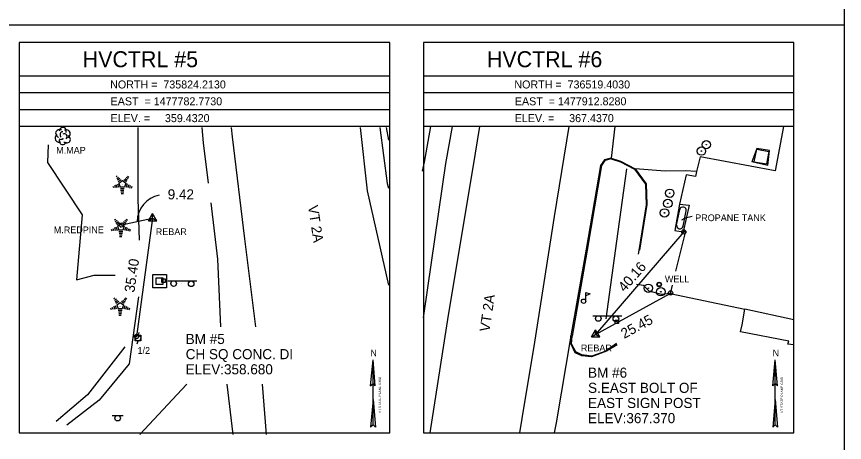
# Model space of a CAD drawing. Extents: x 1478584 to 1479224, y 735365 to 735785.
# Drawn here: x 1478978.7 to 1479224.5, y 735534.2 to 735660.7 of the extents above; entities that cross this region are included whole.
import ezdxf

# ---------------------------------------------------------------- set-up
doc = ezdxf.new("R2010")
doc.units = 0
for name, color, linetype in [('C_A', 7, 'Continuous'), ('CBP', 7, 'Continuous'), ('CPBM', 7, 'Continuous'), ('CPSM', 7, 'Continuous'), ('Default', 7, 'Continuous'), ('DS', 7, 'Continuous'), ('L_C', 7, 'Continuous'), ('LAHR', 7, 'Continuous'), ('LAPB', 7, 'Continuous'), ('LBC', 7, 'Continuous'), ('LBF', 7, 'Continuous'), ('LELB', 7, 'Continuous'), ('LFNC', 7, 'Continuous'), ('LMB', 7, 'Continuous'), ('LS', 7, 'Continuous'), ('LTC', 7, 'Continuous'), ('LTD', 7, 'Continuous'), ('NBL1', 7, 'Continuous'), ('NBL2', 7, 'Continuous'), ('NNA_P', 7, 'Continuous'), ('PET', 7, 'Continuous'), ('PSP', 7, 'Continuous'), ('PSU', 7, 'Continuous'), ('RC', 7, 'Continuous'), ('RDP', 7, 'Continuous'), ('RGP', 7, 'Continuous'), ('SSGN', 7, 'Continuous'), ('U_A', 7, 'Continuous'), ('U_C', 7, 'Continuous'), ('UP', 7, 'Continuous'), ('UWW', 7, 'Continuous')]:
    doc.layers.add(name, color=color, linetype=linetype)

msp = doc.modelspace()

# ---------------------------------------------------------------- linework, layer by layer
at = {"layer": 'CBP'}
for centre, radius in [((1479009.88, 735598.79), 0.625), ((1479009.88, 735598.79), 0.0833), ((1479176.77, 735596.72), 0.625), ((1479176.77, 735596.72), 0.0833), ((1479172.85, 735578.61), 0.625), ((1479172.85, 735578.61), 0.0833), ((1479014.32, 735565.69), 0.625), ((1479014.32, 735565.69), 0.0833)]:
    msp.add_circle(centre, radius, dxfattribs=at)
at = {"layer": 'CPBM'}
for p, q in [((1479021.79, 735581.74), (1479021.79, 735582.74)), ((1479021.79, 735582.74), (1479022.79, 735582.74)), ((1479022.79, 735581.74), (1479021.79, 735581.74)), ((1479022.3, 735582.24), (1479022.3, 735582.24)), ((1479022.3, 735582.24), (1479022.3, 735582.24)), ((1479022.79, 735582.74), (1479022.79, 735581.74)), ((1479156.4, 735569.53), (1479156.4, 735570.53)), ((1479156.4, 735570.53), (1479157.4, 735570.53)), ((1479157.4, 735569.53), (1479156.4, 735569.53)), ((1479156.9, 735570.03), (1479156.9, 735570.03)), ((1479156.9, 735570.03), (1479156.9, 735570.03)), ((1479157.4, 735570.53), (1479157.4, 735569.53))]:
    msp.add_line(p, q, dxfattribs=at)
at = {"layer": 'CPSM'}
for p, q in [((1479017.84, 735600.05), (1479019.09, 735602.21)), ((1479017.84, 735600.05), (1479019.09, 735600.77)), ((1479017.85, 735600.05), (1479019.1, 735602.22)), ((1479017.85, 735600.05), (1479019.1, 735600.77)), ((1479020.34, 735600.05), (1479019.09, 735602.21)), ((1479019.09, 735600.77), (1479019.09, 735602.21)), ((1479019.09, 735600.77), (1479019.09, 735600.77)), ((1479019.09, 735600.77), (1479020.34, 735600.05)), ((1479020.35, 735600.05), (1479019.1, 735602.22)), ((1479019.1, 735600.77), (1479019.1, 735602.22)), ((1479019.1, 735600.77), (1479019.1, 735600.77)), ((1479019.1, 735600.77), (1479020.35, 735600.05)), ((1479017.84, 735600.05), (1479020.34, 735600.05)), ((1479017.85, 735600.05), (1479020.35, 735600.05)), ((1479149.35, 735565.53), (1479150.6, 735567.69)), ((1479149.35, 735565.53), (1479150.6, 735566.25)), ((1479151.85, 735565.53), (1479150.6, 735567.69)), ((1479150.6, 735566.25), (1479150.6, 735567.69)), ((1479150.6, 735566.25), (1479150.6, 735566.25)), ((1479150.6, 735566.25), (1479151.85, 735565.53)), ((1479149.35, 735565.53), (1479151.85, 735565.53))]:
    msp.add_line(p, q, dxfattribs=at)
at = {"layer": 'Default'}
for p, q in [((1479174.63, 735598.77), (1479175.56, 735603.4)), ((1479176.61, 735598.48), (1479177.52, 735603)), ((1479009.88, 735598.79), (1479019.1, 735600.77)), ((1479019.1, 735600.77), (1479014.32, 735565.69)), ((1479176.59, 735598.38), (1479176.61, 735598.48)), ((1479176.77, 735596.72), (1479150.6, 735566.25)), ((1479150.6, 735566.25), (1479172.71, 735578.42))]:
    msp.add_line(p, q, dxfattribs=at)
for centre, radius, start, end in [((1479022.57, 735599.71), 8.08, 100.8349, 179.5195), ((1479176.53, 735603.12), 1, 353.0077, 164.0721), ((1479179.7, 735594.51), 6.76, 93.3569, 122.6023), ((1479175.63, 735598.67), 1.01, 174.3588, 342.721)]:
    msp.add_arc(centre, radius, start, end, dxfattribs=at)
at = {"layer": 'DS'}
for p, q in [((1479019.16, 735584.12), (1479023.16, 735584.12)), ((1479019.16, 735580.12), (1479019.16, 735584.12)), ((1479020.16, 735581.12), (1479020.16, 735583.12)), ((1479020.16, 735583.12), (1479022.16, 735583.12)), ((1479022.16, 735583.12), (1479022.16, 735581.12)), ((1479023.16, 735584.12), (1479023.16, 735580.12)), ((1479022.16, 735581.12), (1479020.16, 735581.12)), ((1479021.17, 735582.12), (1479021.17, 735582.12)), ((1479021.17, 735582.12), (1479021.17, 735582.12)), ((1479023.16, 735580.12), (1479019.16, 735580.12))]:
    msp.add_line(p, q, dxfattribs=at)
at = {"layer": 'LAHR'}
for points in [[(1479153.75, 735570.91), (1479156.85, 735593.93), (1479159.91, 735615.44)], [(1479010.88, 735562.58), (1478999.76, 735548.34), (1478990.41, 735540.43)]]:
    msp.add_lwpolyline(points, dxfattribs=at)
at = {"layer": 'LAPB'}
msp.add_lwpolyline([(1478988.09, 735622.57), (1478987.9, 735617.37), (1478998.19, 735601.76), (1478996.45, 735582.53), (1479001.78, 735583.87), (1479008.01, 735583.9)], dxfattribs=at)
at = {"layer": 'LBC'}
for points in [[(1479206.37, 735627.99), (1479203.93, 735614.91), (1479181.67, 735619.06), (1479180.59, 735614.7), (1479180.23, 735613.14), (1479177.47, 735613.7), (1479175.46, 735604.94), (1479178.35, 735604.65), (1479176.62, 735596.73), (1479177.29, 735596.97), (1479174.35, 735585.07)], [(1479209.4, 735627.98), (1479209.36, 735627.99)], [(1479173.32, 735580.9), (1479172.71, 735578.42), (1479194.91, 735573.74)], [(1479209.4, 735570.65), (1479194.91, 735573.74)]]:
    msp.add_lwpolyline(points, dxfattribs=at)
at = {"layer": 'LBF'}
msp.add_lwpolyline([(1479209.4, 735563.16), (1479207.65, 735563.4), (1479207.96, 735564.27), (1479193.59, 735567), (1479194.06, 735569.09), (1479194.91, 735573.74)], dxfattribs=at)
at = {"layer": 'LELB'}
for points in [[(1479088.43, 735627.72), (1479089.08, 735624.02)], [(1479201.76, 735616.43), (1479202.19, 735620.86), (1479198.44, 735621.54), (1479197.01, 735617.58)], [(1479201.76, 735616.43), (1479197.01, 735617.58)], [(1479162.35, 735615.46), (1479165.56, 735611.01), (1479165.84, 735604.85), (1479163.58, 735591.27)]]:
    msp.add_lwpolyline(points, dxfattribs=at)
at = {"layer": 'LFNC'}
for points in [[(1479015.22, 735594.29), (1479014.82, 735606.55), (1479014.8, 735627.72)], [(1479014.94, 735577.42), (1479012.14, 735557.51), (1479003.2, 735546.79), (1478993.66, 735539.34)]]:
    msp.add_lwpolyline(points, dxfattribs=at)
at = {"layer": 'LMB'}
for p, q in [((1479147.68, 735578.75), (1479148.98, 735578.36)), ((1479147.69, 735576.15), (1479147.69, 735578.75)), ((1479147.69, 735577.85), (1479148.97, 735578.35)), ((1479147.03, 735576.14), (1479147.03, 735576.14))]:
    msp.add_line(p, q, dxfattribs=at)
msp.add_circle((1479147.03, 735576.14), 0.656, dxfattribs=at)
at = {"layer": 'LS'}
for points in [[(1479197.71, 735617.55), (1479198.45, 735621.32), (1479201.97, 735620.63), (1479201.35, 735616.95)], [(1479197.71, 735617.55), (1479201.35, 735616.95)], [(1479175.46, 735604.94), (1479174.1, 735597.15), (1479176.62, 735596.73)]]:
    msp.add_lwpolyline(points, dxfattribs=at)
at = {"layer": 'LTC'}
for p, q in [((1479008.24, 735613.09), (1479008.6, 735613.34)), ((1479008.45, 735612.62), (1479008.98, 735613)), ((1479008.66, 735612.15), (1479009.36, 735612.67)), ((1479010.9, 735612.63), (1479011.58, 735612.14)), ((1479011.27, 735612.98), (1479011.82, 735612.58)), ((1479011.64, 735613.33), (1479012.06, 735613.02)), ((1479007.27, 735610.36), (1479007.43, 735609.9)), ((1479007.73, 735610.58), (1479007.94, 735609.93)), ((1479008.18, 735610.8), (1479008.46, 735609.96)), ((1479008.64, 735611.01), (1479008.97, 735609.99)), ((1479008.87, 735611.69), (1479009.75, 735612.33)), ((1479009.09, 735611.23), (1479010.11, 735611.97)), ((1479009.09, 735611.23), (1479009.48, 735610.04)), ((1479010.11, 735611.97), (1479011.1, 735611.24)), ((1479010.53, 735612.28), (1479011.34, 735611.69)), ((1479011.1, 735611.24), (1479010.71, 735610.04)), ((1479011.54, 735610.97), (1479011.2, 735609.93)), ((1479011.99, 735610.72), (1479011.7, 735609.84)), ((1479012.43, 735610.47), (1479012.19, 735609.74)), ((1479012.87, 735610.22), (1479012.69, 735609.65)), ((1479010.71, 735610.04), (1479009.48, 735610.04)), ((1479010.67, 735609.54), (1479009.53, 735609.54)), ((1479010.59, 735609.04), (1479009.6, 735609.04)), ((1479010.51, 735608.54), (1479009.67, 735608.54)), ((1479010.42, 735608.04), (1479009.75, 735608.04)), ((1479007.79, 735600.28), (1479008.15, 735600.53)), ((1479011.19, 735600.52), (1479011.61, 735600.21)), ((1479007.28, 735597.77), (1479007.49, 735597.12)), ((1479007.74, 735597.99), (1479008.01, 735597.15)), ((1479008, 735599.81), (1479008.53, 735600.2)), ((1479008.19, 735598.21), (1479008.52, 735597.19)), ((1479008.21, 735599.35), (1479008.92, 735599.86)), ((1479008.42, 735598.88), (1479009.3, 735599.52)), ((1479008.65, 735598.42), (1479009.66, 735599.16)), ((1479008.65, 735598.42), (1479009.03, 735597.23)), ((1479009.66, 735599.16), (1479010.66, 735598.43)), ((1479010.08, 735599.47), (1479010.89, 735598.88)), ((1479010.66, 735598.43), (1479010.26, 735597.23)), ((1479010.45, 735599.82), (1479011.13, 735599.33)), ((1479011.09, 735598.16), (1479010.76, 735597.12)), ((1479010.82, 735600.17), (1479011.37, 735599.77)), ((1479011.54, 735597.91), (1479011.25, 735597.03)), ((1479006.83, 735597.56), (1479006.98, 735597.09)), ((1479010.26, 735597.23), (1479009.03, 735597.23)), ((1479010.23, 735596.73), (1479009.08, 735596.73)), ((1479010.14, 735596.23), (1479009.15, 735596.23)), ((1479010.06, 735595.73), (1479009.23, 735595.73)), ((1479011.98, 735597.66), (1479011.75, 735596.93)), ((1479012.43, 735597.41), (1479012.24, 735596.84)), ((1479009.98, 735595.23), (1479009.3, 735595.23)), ((1479007.58, 735576.92), (1479007.94, 735577.17)), ((1479007.79, 735576.45), (1479008.32, 735576.84)), ((1479008, 735575.99), (1479008.71, 735576.5)), ((1479008.21, 735575.52), (1479009.09, 735576.16)), ((1479008.44, 735575.07), (1479009.45, 735575.8)), ((1479009.45, 735575.8), (1479010.44, 735575.07)), ((1479009.87, 735576.11), (1479010.68, 735575.52)), ((1479010.24, 735576.46), (1479010.92, 735575.97)), ((1479010.61, 735576.81), (1479011.16, 735576.41)), ((1479010.98, 735577.16), (1479011.4, 735576.85)), ((1479006.61, 735574.2), (1479006.77, 735573.73)), ((1479007.07, 735574.41), (1479007.28, 735573.76)), ((1479007.53, 735574.63), (1479007.8, 735573.79)), ((1479007.98, 735574.85), (1479008.31, 735573.83)), ((1479008.44, 735575.07), (1479008.82, 735573.87)), ((1479010.05, 735573.87), (1479008.82, 735573.87)), ((1479010.01, 735573.37), (1479008.87, 735573.37)), ((1479010.44, 735575.07), (1479010.05, 735573.87)), ((1479010.88, 735574.8), (1479010.54, 735573.76)), ((1479011.33, 735574.55), (1479011.04, 735573.67)), ((1479011.77, 735574.3), (1479011.53, 735573.57)), ((1479012.22, 735574.05), (1479012.03, 735573.48)), ((1479009.93, 735572.87), (1479008.94, 735572.87)), ((1479009.85, 735572.37), (1479009.02, 735572.37)), ((1479009.76, 735571.87), (1479009.09, 735571.87))]:
    msp.add_line(p, q, dxfattribs=at)
at = {"layer": 'LTD'}
msp.add_line((1478992.39, 735625.24), (1478992.39, 735625.24), dxfattribs=at)
msp.add_line((1478992.39, 735625.24), (1478992.39, 735625.24), dxfattribs=at)
msp.add_arc((1478992.43, 735626.67), 1.05, 335.5272, 180.9563, dxfattribs=at)
for centre, major_axis, ratio, start_param, end_param in [((1478991.59, 735625.91), (1.21, -0.51), 0.895232, 1.570796, 4.712389), ((1478991.3, 735624.53), (0.58, -1.04), 0.959034, 3.141593, 6.283185), ((1478992.18, 735625.7), (-0.208, -0.792), 0.645439, 3.141593, 6.283185), ((1478992.89, 735625.07), (-0.5, 0.667), 0.989748, 3.141593, 6.283185), ((1478993.39, 735624.41), (-1.09, 0.79), 0.841452, 1.570796, 4.712389), ((1478993.43, 735625.82), (-1.14, -0.48), 0.949671, 1.570796, 4.712389), ((1478992.39, 735623.74), (0.26, 1.06), 0.942809, 1.570796, 4.712389), ((1478991.93, 735624.49), (-0.625, -0.083), 0.423636, 0, 3.141593)]:
    msp.add_ellipse(centre, major_axis=major_axis, ratio=ratio, start_param=start_param, end_param=end_param, dxfattribs=at)
at = {"layer": 'NBL1'}
msp.add_lwpolyline([(1478584.46, 735364.52), (1479224.46, 735364.52), (1479224.46, 735784.52), (1478584.46, 735784.52)], close=True, dxfattribs=at)
at = {"layer": 'NBL2'}
for p, q in [((1478584.46, 735658.18), (1479224.46, 735658.18)), ((1479089.46, 735643.02), (1478979.46, 735643.02)), ((1479209.46, 735643.02), (1479099.46, 735643.02)), ((1479089.46, 735638.02), (1478979.46, 735638.02)), ((1479209.46, 735638.02), (1479099.46, 735638.02)), ((1479089.46, 735633.02), (1478979.46, 735633.02)), ((1479209.46, 735633.02), (1479099.46, 735633.02)), ((1479089.46, 735628.02), (1478979.46, 735628.02)), ((1479209.46, 735628.02), (1479099.46, 735628.02))]:
    msp.add_line(p, q, dxfattribs=at)
for points in [[(1478979.46, 735537.02), (1479089.46, 735537.02), (1479089.46, 735653.02), (1478979.46, 735653.02)], [(1479099.46, 735537.02), (1479209.46, 735537.02), (1479209.46, 735653.02), (1479099.46, 735653.02)]]:
    msp.add_lwpolyline(points, close=True, dxfattribs=at)
at = {"layer": 'NNA_P'}
for p, q in [((1479083.81, 735550.98), (1479084.51, 735558.77)), ((1479084.51, 735539.39), (1479084.51, 735558.77)), ((1479085.2, 735550.98), (1479084.51, 735558.77)), ((1479203.21, 735550.98), (1479203.9, 735558.77)), ((1479203.91, 735539.39), (1479203.9, 735558.77)), ((1479204.6, 735550.98), (1479203.9, 735558.77)), ((1479083.81, 735550.98), (1479084.51, 735551.74)), ((1479085.2, 735550.98), (1479084.51, 735551.74)), ((1479203.21, 735550.98), (1479203.91, 735551.74)), ((1479204.6, 735550.98), (1479203.91, 735551.74)), ((1479084.51, 735546.92), (1479083.79, 735538.75)), ((1479084.51, 735546.92), (1479085.23, 735538.75)), ((1479203.91, 735546.92), (1479203.19, 735538.75)), ((1479203.91, 735546.92), (1479204.63, 735538.75)), ((1479084.51, 735539.39), (1479083.79, 735538.75)), ((1479084.51, 735539.39), (1479085.23, 735538.75)), ((1479203.91, 735539.39), (1479203.19, 735538.75)), ((1479203.91, 735539.39), (1479204.63, 735538.75))]:
    msp.add_line(p, q, dxfattribs=at)
at = {"layer": 'PET'}
for points in [[(1479049.68, 735568.56), (1479046.42, 735594.7), (1479042.82, 735624.97), (1479042.51, 735627.72)], [(1479080.66, 735627.72), (1479082.75, 735608.94), (1479089.08, 735580.86)], [(1479101.48, 735537.02), (1479106.91, 735571.98), (1479114.26, 735615.88), (1479116.19, 735627.99)], [(1479142.67, 735627.99), (1479138.28, 735601.33), (1479132.46, 735563.94), (1479128.69, 735541.31), (1479127.95, 735537.02)], [(1479029.21, 735551.52), (1479029.12, 735551.38), (1479015.28, 735536.54)], [(1479052.91, 735536.54), (1479051.75, 735551.52)]]:
    msp.add_lwpolyline(points, dxfattribs=at)
at = {"layer": 'PSP'}
for points in [[(1479035.7, 735611.2), (1479034.23, 735623.16), (1479033.75, 735627.72)], [(1479086.55, 735627.72), (1479088.75, 735611.08), (1479089.08, 735609.73)], [(1479099.46, 735571.19), (1479099.74, 735572.61), (1479106.16, 735617.04), (1479108.07, 735627.99)], [(1479156.32, 735627.99), (1479155.21, 735618.63), (1479153.23, 735618.09), (1479152.06, 735616.46), (1479147.82, 735591.58), (1479143.26, 735565.82), (1479138.92, 735540.07), (1479138.29, 735537.02)], [(1479039.37, 735568.56), (1479038.47, 735588.63), (1479036.42, 735605.35)], [(1479042.96, 735536.54), (1479041.24, 735551.52)]]:
    msp.add_lwpolyline(points, dxfattribs=at)
at = {"layer": 'PSU'}
msp.add_lwpolyline([(1479099.23, 735614.74), (1479099.82, 735617.47), (1479101.7, 735627.99)], dxfattribs=at)
at = {"layer": 'RC'}
for points in [[(1479155.23, 735618.46), (1479153.35, 735617.97), (1479152.3, 735616.49), (1479148.08, 735591.33), (1479143.62, 735565.75)], [(1479155.23, 735618.46), (1479158, 735617.52), (1479162.16, 735615.37), (1479165.36, 735610.91), (1479165.62, 735604.81), (1479163.43, 735591.23), (1479163.25, 735590.08)], [(1479156.81, 735563.57), (1479153.64, 735561.33), (1479149.46, 735559.82), (1479146.52, 735560.17), (1479144.72, 735561.06), (1479143.41, 735563.44), (1479143.62, 735565.75)]]:
    msp.add_lwpolyline(points, dxfattribs=at)
at = {"layer": 'RDP'}
for points in [[(1479155.21, 735618.63), (1479157.98, 735617.74), (1479162.35, 735615.46)], [(1479180.59, 735614.7), (1479177.24, 735614.91), (1479171.24, 735614.75), (1479162.35, 735615.46)], [(1479172.71, 735578.42), (1479170.11, 735578.13), (1479166.47, 735579.13), (1479164.78, 735580.79), (1479162.75, 735581.11)], [(1479156.97, 735563.23), (1479153.81, 735561.27), (1479149.37, 735559.67), (1479146.46, 735559.89), (1479144.55, 735560.81), (1479143.29, 735563.39), (1479143.26, 735565.82)]]:
    msp.add_lwpolyline(points, dxfattribs=at)
at = {"layer": 'RGP'}
for p, q in [((1479183.46, 735622.63), (1479183.46, 735622.63)), ((1479182, 735620.74), (1479182, 735620.74)), ((1479172.59, 735608.21), (1479172.59, 735608.21)), ((1479172.02, 735605.18), (1479172.02, 735605.18)), ((1479171.04, 735602.36), (1479171.04, 735602.36)), ((1479166.25, 735580), (1479166.25, 735580)), ((1479169.95, 735578.95), (1479169.95, 735578.95))]:
    msp.add_line(p, q, dxfattribs=at)
for centre, radius in [((1479183.46, 735622.63), 1.25), ((1479183.46, 735622.63), 0.0833), ((1479182, 735620.74), 1.25), ((1479182, 735620.74), 0.0833), ((1479172.59, 735608.21), 1.25), ((1479172.59, 735608.21), 0.0833), ((1479172.02, 735605.18), 1.25), ((1479172.02, 735605.18), 0.0833), ((1479171.04, 735602.36), 1.25), ((1479171.04, 735602.36), 0.0833), ((1479166.25, 735580), 1.25), ((1479166.25, 735580), 0.0833), ((1479169.95, 735578.95), 1.25), ((1479169.95, 735578.95), 0.0833)]:
    msp.add_circle(centre, radius, dxfattribs=at)
at = {"layer": 'SSGN'}
for p, q in [((1479023.65, 735582.22), (1479032.25, 735582.22)), ((1479027.68, 735581.32), (1479027.68, 735581.32)), ((1479149.73, 735571.83), (1479158.33, 735571.83)), ((1479153.75, 735570.93), (1479153.75, 735570.93)), ((1479007.05, 735542.24), (1479010.38, 735542.24)), ((1479008.7, 735541.4), (1479008.7, 735541.4))]:
    msp.add_line(p, q, dxfattribs=at)
for centre in [(1479025.32, 735581.39), (1479030.53, 735581.32), (1479151.39, 735571), (1479156.61, 735570.93), (1479008.7, 735541.4)]:
    msp.add_circle(centre, 0.833, dxfattribs=at)
at = {"layer": 'UP'}
for p, q in [((1479013.93, 735564.36), (1479013.93, 735566.02)), ((1479013.93, 735566.02), (1479015.59, 735566.02)), ((1479015.01, 735566.86), (1479014.76, 735566.02)), ((1479015.59, 735566.02), (1479015.59, 735564.36)), ((1479015.59, 735564.36), (1479013.93, 735564.36)), ((1479014.51, 735563.52), (1479014.76, 735564.36)), ((1479014.76, 735565.19), (1479014.76, 735565.19))]:
    msp.add_line(p, q, dxfattribs=at)
msp.add_circle((1479014.76, 735565.19), 0.833, dxfattribs=at)
at = {"layer": 'UWW'}
for radius in [0.667, 0.625, 0.583, 0.542]:
    msp.add_circle((1479169.47, 735581.12), radius, dxfattribs=at)

# ---------------------------------------------------------------- texts
at = {"layer": 'C_A'}
for p in [(1479020.03, 735595.77), (1479146.22, 735561.25)]:
    msp.add_text('REBAR', height=2, dxfattribs=at).set_placement(p)
at = {"layer": 'Default'}
for s, rotation, p in [('9.42', 359.7881, (1479023.56, 735606.39)), ('VT 2A', 278.6866, (1479065.19, 735604.4)), ('35.40', 81.6808, (1479013.66, 735578.6)), ('40.16', 48.7194, (1479159.22, 735578.68)), ('VT 2A', 81.6494, (1479119.08, 735566.91)), ('25.45', 28.4511, (1479159.1, 735564.94))]:
    msp.add_text(s, height=3, rotation=rotation, dxfattribs=at).set_placement(p)
at = {"layer": 'L_C'}
for s, p in [('M.MAP', (1478990.46, 735619.99)), ('M.REDPINE', (1478989.75, 735596.34))]:
    msp.add_text(s, height=2, dxfattribs=at).set_placement(p)
at = {"layer": 'LTC'}
for p in [(1479009.99, 735610.98), (1479009.54, 735598.17), (1479009.33, 735574.81)]:
    msp.add_text('.', height=1.04, rotation=270, dxfattribs=at).set_placement(p)
at = {"layer": 'NBL2'}
for s, height, p in [('      HVCTRL #5     ', 4.75, (1478987.75, 735645.64)), ('      HVCTRL #6     ', 4.75, (1479107.75, 735645.64)), ('NORTH =  735824.2130', 2.375, (1479006.48, 735639.33)), ('NORTH =  736519.4030', 2.375, (1479126.48, 735639.33)), ('EAST  = 1477782.7730', 2.375, (1479006.62, 735634.33)), ('EAST  = 1477912.8280', 2.375, (1479126.62, 735634.33)), ('ELEV. =     359.4320', 2.375, (1479006.59, 735629.33)), ('ELEV. =     367.4370', 2.375, (1479126.59, 735629.33)), ('BM #5', 3, (1479028.91, 735563.42)), ('CH SQ CONC. DI', 3, (1479028.91, 735558.92)), ('ELEV:358.680', 3, (1479028.91, 735554.42)), ('BM #6', 3, (1479148.35, 735553.42)), ('S.EAST BOLT OF ', 3, (1479148.35, 735548.92)), ('EAST SIGN POST ', 3, (1479148.35, 735544.42)), ('ELEV:367.370', 3, (1479148.35, 735539.92))]:
    msp.add_text(s, height=height, dxfattribs=at).set_placement(p)
at = {"layer": 'NNA_P'}
for p in [(1479083.75, 735559.78), (1479203.14, 735559.78)]:
    msp.add_text('N', height=1.97, dxfattribs=at).set_placement(p)
for p in [(1479086.86, 735542.96), (1479206.26, 735542.96)]:
    msp.add_text('VT STATE PLANE GRID', height=0.7, rotation=90.0204, dxfattribs=at).set_placement(p)
at = {"layer": 'U_A'}
for s, p in [('PROPANE TANK', (1479180.16, 735599.92)), ('WELL', (1479171.16, 735581.76))]:
    msp.add_text(s, height=2, dxfattribs=at).set_placement(p)
at = {"layer": 'U_C'}
msp.add_text('1/2', height=2, dxfattribs=at).set_placement((1479014.6, 735560.51))

doc.saveas('drawing.dxf')
